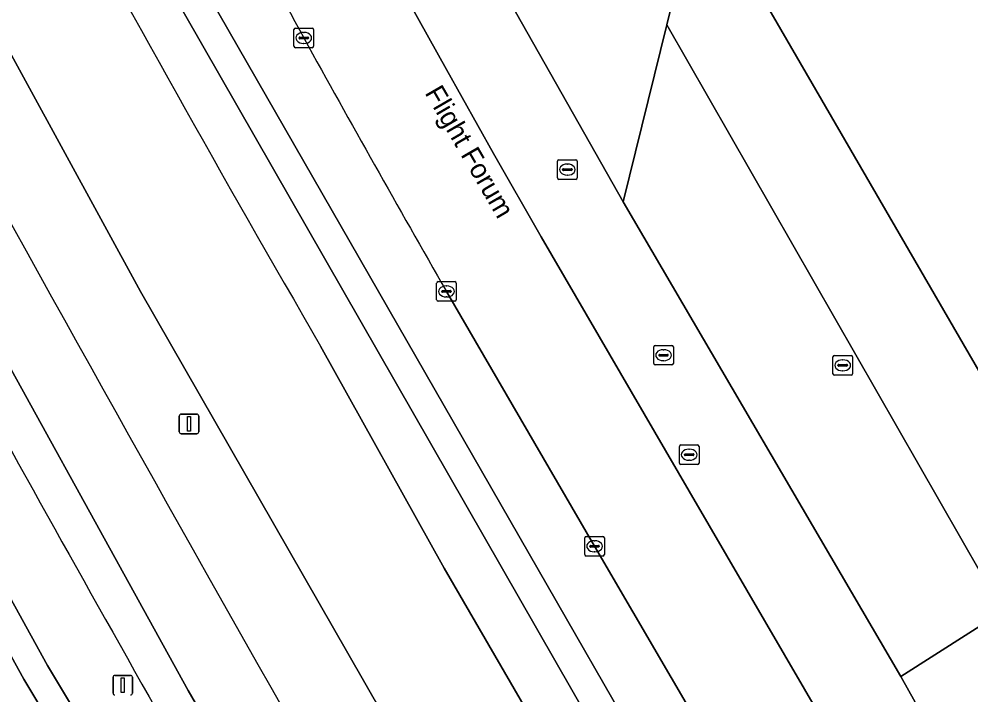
# Model space of a CAD drawing. Extents: x 155018 to 156648, y 383979 to 385733.
# Drawn here: x 155914.11 to 155962.62, y 384865.44 to 384899.91 of the extents above; entities that cross this region are included whole.
import ezdxf

# ---------------------------------------------------------------- set-up
doc = ezdxf.new("R2010")
doc.units = 0
for name, color, linetype in [('IMGEO_Berm_groen', 7, 'Continuous'), ('IMGEO_Fietspad_gesloten', 7, 'Continuous'), ('IMGEO_Greppel_droge_sloot', 7, 'Continuous'), ('IMGEO_Groenvoorziening', 7, 'Continuous'), ('IMGEO_Kolk', 7, 'Continuous'), ('IMGEO_Lichtmast', 7, 'Continuous'), ('IMGEO_Oever', 7, 'Continuous'), ('IMGEO_Openbare_ruimte_label', 7, 'Continuous'), ('IMGEO_Parkeervlak_gesloten', 7, 'Continuous'), ('IMGEO_Parkeervlak_open', 7, 'Continuous'), ('IMGEO_Rijbaan_lokaal_gesloten', 7, 'Continuous'), ('IMGEO_Rijbaan_lokaal_open', 7, 'Continuous'), ('IMGEO_Rijbaan_regionaal_gesloten', 7, 'Continuous'), ('IMGEO_Rioolput', 7, 'Continuous'), ('IMGEO_Verkeerseiland_groen', 7, 'Continuous'), ('IMGEO_Voetpad_gesloten', 7, 'Continuous'), ('IMGEO_Waterloop', 7, 'Continuous')]:
    doc.layers.add(name, color=color, linetype=linetype)

msp = doc.modelspace()

# ---------------------------------------------------------------- linework, layer by layer
at = {"layer": 'IMGEO_Berm_groen'}
for points in [[(155968.307, 384802.15), (155931.668, 384866.172), (155920.302, 384886.009), (155902.596, 384918.444), (155898.732, 384925.896), (155894.98, 384933.155)], [(155970.759, 384878.339), (155969.52, 384880.471), (155965.298, 384878.033), (155951.454, 384901.936), (155956.211, 384904.782), (155955.257, 384906.561), (155953.497, 384906.937), (155948.14, 384903.802), (155947.503, 384901.164), (155947.122, 384899.613), (155964.252, 384869.701), (155964.8, 384870.05), (155970.427, 384873.861)]]:
    msp.add_lwpolyline(points, dxfattribs=at)
msp.add_arc((158231.037, 386171.485), 2648.321, 208.928524, 210.788417, dxfattribs=at)
at = {"layer": 'IMGEO_Fietspad_gesloten'}
msp.add_lwpolyline([(155891.806, 384922.174), (155901.33, 384904.485), (155909.95, 384888.824), (155922.729, 384865.669), (155940.418, 384835.124), (155959.664, 384802.736), (155961.452, 384799.64), (155970.449, 384784.821), (155975.409, 384776.674)], dxfattribs=at)
msp.add_arc((158231.037, 386171.485), 2648.321, 208.928524, 210.788417, dxfattribs=at)
at = {"layer": 'IMGEO_Greppel_droge_sloot'}
for points in [[(155907.015, 384928.97), (155911.536, 384920.207), (155922.534, 384900.162), (155961.154, 384832.74)], [(155962.543, 384833.543), (155923.838, 384901.004), (155912.886, 384920.904), (155908.561, 384929.213)]]:
    msp.add_lwpolyline(points, dxfattribs=at)
at = {"layer": 'IMGEO_Groenvoorziening'}
msp.add_lwpolyline([(155897.525, 384899.54), (155897.874, 384899.054), (155915.552, 384866.936), (155929.251, 384844.105), (155931.997, 384845.617)], dxfattribs=at)
msp.add_arc((157919.27, 385992.931), 2294.686, 208.789811, 209.999159, dxfattribs=at)
at = {"layer": 'IMGEO_Kolk'}
for p, q in [((155928.119, 384898.515), (155928.119, 384899.367)), ((155928.194, 384899.441), (155929.046, 384899.441)), ((155928.607, 384899.221), (155928.632, 384899.221)), ((155929.12, 384899.367), (155929.12, 384898.515)), ((155928.378, 384898.935), (155928.378, 384898.947)), ((155928.816, 384898.898), (155928.418, 384898.898)), ((155928.421, 384898.984), (155928.819, 384898.984)), ((155928.862, 384898.947), (155928.862, 384898.935)), ((155929.046, 384898.441), (155928.194, 384898.441)), ((155928.63, 384898.661), (155928.605, 384898.661)), ((155935.392, 384885.588), (155935.392, 384886.44)), ((155935.467, 384886.514), (155936.319, 384886.514)), ((155935.88, 384886.294), (155935.905, 384886.294)), ((155936.393, 384886.44), (155936.393, 384885.588)), ((155935.651, 384886.008), (155935.651, 384886.02)), ((155936.089, 384885.971), (155935.691, 384885.971)), ((155935.694, 384886.057), (155936.092, 384886.057)), ((155935.903, 384885.734), (155935.878, 384885.734)), ((155936.135, 384886.02), (155936.135, 384886.008)), ((155936.319, 384885.514), (155935.467, 384885.514)), ((155943.013, 384873.52), (155943.865, 384873.52)), ((155942.938, 384872.594), (155942.938, 384873.446)), ((155943.197, 384873.014), (155943.197, 384873.026)), ((155943.24, 384873.063), (155943.638, 384873.063)), ((155943.426, 384873.3), (155943.451, 384873.3)), ((155943.681, 384873.026), (155943.681, 384873.014)), ((155943.939, 384873.446), (155943.939, 384872.594)), ((155943.865, 384872.52), (155943.013, 384872.52)), ((155943.635, 384872.977), (155943.237, 384872.977)), ((155943.449, 384872.74), (155943.424, 384872.74))]:
    msp.add_line(p, q, dxfattribs=at)
for points in [[(155928.119, 384898.515), (155928.119, 384899.367)], [(155928.194, 384899.441), (155929.046, 384899.441)], [(155929.12, 384899.367), (155929.12, 384898.515)], [(155929.046, 384898.441), (155928.194, 384898.441)], [(155935.392, 384885.588), (155935.392, 384886.44)], [(155935.467, 384886.514), (155936.319, 384886.514)], [(155936.393, 384886.44), (155936.393, 384885.588)], [(155936.319, 384885.514), (155935.467, 384885.514)], [(155943.013, 384873.52), (155943.865, 384873.52)], [(155942.938, 384872.594), (155942.938, 384873.446)], [(155943.939, 384873.446), (155943.939, 384872.594)], [(155943.865, 384872.52), (155943.013, 384872.52)]]:
    msp.add_lwpolyline(points, dxfattribs=at)
for centre, radius, start, end in [((155928.196, 384899.365), 0.0765, 91.552, 178.448), ((155928.196, 384899.365), 0.0765, 91.552, 178.448), ((155929.044, 384899.365), 0.0765, 1.552, 88.448), ((155929.044, 384899.365), 0.0765, 1.552, 88.448), ((155928.418, 384898.944), 0.0403, 85.8775, 175.7526), ((155928.415, 384898.934), 0.0366, 178.938, 274.7102), ((155928.819, 384898.941), 0.043, 264.8664, 352.4533), ((155928.823, 384898.946), 0.0386, 1.7309, 96.639), ((155928.196, 384898.517), 0.0765, 181.552, 268.448), ((155928.196, 384898.517), 0.0765, 181.552, 268.448), ((155929.044, 384898.517), 0.0765, 271.552, 358.448), ((155929.044, 384898.517), 0.0765, 271.552, 358.448), ((155935.469, 384886.438), 0.0765, 91.552, 178.448), ((155935.469, 384886.438), 0.0765, 91.552, 178.448), ((155936.317, 384886.438), 0.0765, 1.552, 88.448), ((155936.317, 384886.438), 0.0765, 1.552, 88.448), ((155935.691, 384886.017), 0.0403, 85.8775, 175.7526), ((155935.688, 384886.007), 0.0366, 178.938, 274.7102), ((155936.092, 384886.014), 0.043, 264.8664, 352.4533), ((155936.096, 384886.019), 0.0386, 1.7309, 96.639), ((155935.469, 384885.59), 0.0765, 181.552, 268.448), ((155935.469, 384885.59), 0.0765, 181.552, 268.448), ((155936.317, 384885.59), 0.0765, 271.552, 358.448), ((155936.317, 384885.59), 0.0765, 271.552, 358.448), ((155943.015, 384873.444), 0.0765, 91.552, 178.448), ((155943.015, 384873.444), 0.0765, 91.552, 178.448), ((155943.863, 384873.444), 0.0765, 1.552, 88.448), ((155943.863, 384873.444), 0.0765, 1.552, 88.448), ((155943.237, 384873.023), 0.0403, 85.8775, 175.7526), ((155943.234, 384873.013), 0.0366, 178.938, 274.7102), ((155943.638, 384873.02), 0.043, 264.8664, 352.4533), ((155943.642, 384873.025), 0.0386, 1.7309, 96.639), ((155943.015, 384872.596), 0.0765, 181.552, 268.448), ((155943.015, 384872.596), 0.0765, 181.552, 268.448), ((155943.863, 384872.596), 0.0765, 271.552, 358.448), ((155943.863, 384872.596), 0.0765, 271.552, 358.448)]:
    msp.add_arc(centre, radius, start, end, dxfattribs=at)
for centre, major_axis, ratio, start_param, end_param in [((155928.606, 384898.941), (-0.387, 0.002), 0.722429, 4.712389, 7.853982), ((155928.631, 384898.941), (-0.39, 0.002), 0.717154, 1.570796, 4.712389), ((155935.879, 384886.014), (-0.387, 0.002), 0.722429, 4.712389, 7.853982), ((155935.904, 384886.014), (-0.39, 0.002), 0.717154, 1.570796, 4.712389), ((155943.425, 384873.02), (-0.387, 0.002), 0.722429, 4.712389, 7.853982), ((155943.45, 384873.02), (-0.39, 0.002), 0.717154, 1.570796, 4.712389)]:
    msp.add_ellipse(centre, major_axis=major_axis, ratio=ratio, start_param=start_param, end_param=end_param, dxfattribs=at)
at = {"layer": 'IMGEO_Lichtmast'}
for p, q in [((155922.276, 384878.86), (155922.276, 384879.66)), ((155922.276, 384879.66), (155922.276, 384878.86)), ((155922.376, 384879.76), (155923.166, 384879.76)), ((155923.166, 384879.76), (155922.376, 384879.76)), ((155923.266, 384879.66), (155923.266, 384878.86)), ((155923.266, 384878.86), (155923.266, 384879.66)), ((155923.166, 384878.76), (155922.376, 384878.76)), ((155922.376, 384878.76), (155923.166, 384878.76)), ((155918.897, 384865.537), (155918.897, 384866.337)), ((155918.897, 384866.337), (155918.897, 384865.537)), ((155918.997, 384866.437), (155919.787, 384866.437)), ((155919.787, 384866.437), (155918.997, 384866.437)), ((155919.887, 384866.337), (155919.887, 384865.537)), ((155919.887, 384865.537), (155919.887, 384866.337))]:
    msp.add_line(p, q, dxfattribs=at)
for points in [[(155922.696, 384879.635), (155922.846, 384879.635), (155922.846, 384878.885), (155922.696, 384878.885), (155922.696, 384879.635)], [(155919.317, 384866.312), (155919.467, 384866.312), (155919.467, 384865.562), (155919.317, 384865.562), (155919.317, 384866.312)]]:
    msp.add_lwpolyline(points, dxfattribs=at)
for centre, start, end in [((155922.376, 384879.66), 90, 180), ((155922.376, 384879.66), 90, 180), ((155923.166, 384879.66), 0, 90), ((155923.166, 384879.66), 360, 90), ((155922.376, 384878.86), 180, 270), ((155922.376, 384878.86), 180, 270), ((155923.166, 384878.86), 270, 0), ((155923.166, 384878.86), 270, 0), ((155918.997, 384866.337), 90, 180), ((155918.997, 384866.337), 90, 180), ((155919.787, 384866.337), 0, 90), ((155919.787, 384866.337), 360, 90), ((155918.997, 384865.537), 180, 270), ((155918.997, 384865.537), 180, 270), ((155919.787, 384865.537), 270, 0), ((155919.787, 384865.537), 270, 0)]:
    msp.add_arc(centre, 0.1, start, end, dxfattribs=at)
at = {"layer": 'IMGEO_Oever'}
for points in [[(155965.324, 384781.723), (155958.557, 384793.522), (155956.272, 384797.883), (155953.363, 384803.433), (155946.914, 384814.668), (155941.514, 384823.667), (155929.251, 384844.105), (155915.552, 384866.936), (155897.874, 384899.054), (155897.525, 384899.54)], [(155896.704, 384898.316), (155914.355, 384866.248), (155928.067, 384843.395), (155940.33, 384822.957), (155945.723, 384813.969), (155952.153, 384802.769), (155955.049, 384797.242), (155957.308, 384792.919), (155960.889, 384784.915)]]:
    msp.add_lwpolyline(points, dxfattribs=at)
at = {"layer": 'IMGEO_Parkeervlak_gesloten'}
for points in [[(155981.253, 384820.042), (155973.203, 384833.364), (155971.597, 384835.865), (155963.834, 384849.111), (155956.062, 384862.435), (155948.253, 384875.822), (155940.718, 384888.798), (155938.292, 384893.055), (155935.89, 384897.326), (155933.51, 384901.609), (155931.147, 384906.043), (155928.826, 384910.5), (155926.547, 384914.979), (155926.098, 384915.88), (155925.651, 384916.782), (155925.205, 384917.685), (155918.109, 384932.502), (155912.529, 384944.815)], [(155980.921, 384915.2), (155979.219, 384918.159), (155974.453, 384915.535), (155973.423, 384917.252), (155973.946, 384918.903), (155967.476, 384915.117), (155969.12, 384914.261), (155969.886, 384912.863), (155960.603, 384907.493), (155959.569, 384909.203), (155959.871, 384910.667), (155953.497, 384906.937), (155955.257, 384906.561), (155956.211, 384904.782), (155951.454, 384901.936), (155965.298, 384878.033), (155969.52, 384880.471), (155970.759, 384878.339)], [(155935.893, 384886.014), (155943.439, 384873.02), (155951.25, 384859.629), (155959.025, 384846.299), (155966.849, 384832.951), (155969.799, 384828.356), (155972.403, 384824.534), (155976.142, 384819.299), (155978.271, 384816.549), (155980.512, 384819.861), (155980.596, 384819.986)]]:
    msp.add_lwpolyline(points, dxfattribs=at)
for centre, radius, start, end in [((156400.107, 385153.11), 535.632, 206.69467, 208.32823), ((156736.167, 385344.774), 922.442, 208.902362, 209.823666)]:
    msp.add_arc(centre, radius, start, end, dxfattribs=at)
at = {"layer": 'IMGEO_Parkeervlak_open'}
msp.add_lwpolyline([(155947.122, 384899.613), (155944.902, 384890.583), (155959.041, 384866.377), (155964.252, 384869.701)], close=True, dxfattribs=at)
at = {"layer": 'IMGEO_Rijbaan_lokaal_gesloten'}
for points in [[(155912.529, 384944.815), (155918.109, 384932.502), (155925.205, 384917.685), (155925.651, 384916.782), (155926.098, 384915.88), (155926.547, 384914.979), (155928.826, 384910.5), (155931.147, 384906.043), (155933.51, 384901.609), (155935.89, 384897.326), (155938.292, 384893.055), (155940.718, 384888.798), (155948.253, 384875.822), (155956.062, 384862.435), (155963.834, 384849.111), (155971.597, 384835.865), (155973.203, 384833.364), (155981.253, 384820.042), (155983.336, 384816.735), (155984.592, 384814.908), (155987.12, 384811.227), (155988.5, 384809.261), (155990.13, 384807.18)], [(155976.357, 384836.745), (155965.559, 384855.153), (155963.825, 384857.831), (155959.041, 384866.377), (155944.902, 384890.583), (155938.324, 384902.21), (155934.031, 384910.194)], [(155993.943, 384883.464), (156014.432, 384895.282), (156010.159, 384902.636), (156005.328, 384899.852), (156004.508, 384901.232), (156002.81, 384900.264), (155997.133, 384896.963), (155997.854, 384895.599), (155994.407, 384893.715), (155993.069, 384892.655), (155983.572, 384887.264), (155982.48, 384886.602), (155982.301, 384886.448), (155983.278, 384884.804), (155983.874, 384882.97), (155981.889, 384881.625), (155980.413, 384880.626), (155979.235, 384879.828), (155970.427, 384873.861), (155964.8, 384870.05), (155964.252, 384869.701), (155959.041, 384866.377), (155963.825, 384857.831), (155964.057, 384860.389)]]:
    msp.add_lwpolyline(points, dxfattribs=at)
at = {"layer": 'IMGEO_Rijbaan_lokaal_open'}
msp.add_lwpolyline([(155970.829, 384923.546), (155950.99, 384911.918), (155943.564, 384907.565), (155942.381, 384907.891), (155934.031, 384910.194), (155938.324, 384902.21), (155944.902, 384890.583), (155947.122, 384899.613), (155947.503, 384901.164), (155948.14, 384903.802), (155953.497, 384906.937), (155959.871, 384910.667), (155967.476, 384915.117)], dxfattribs=at)
at = {"layer": 'IMGEO_Rijbaan_regionaal_gesloten'}
for points in [[(155894.98, 384933.155), (155898.732, 384925.896), (155902.596, 384918.444), (155920.302, 384886.009), (155931.668, 384866.172), (155968.307, 384802.15)], [(155958.037, 384833.375), (155954.35, 384839.888), (155935.774, 384871.908), (155929.479, 384883.226)]]:
    msp.add_lwpolyline(points, dxfattribs=at)
msp.add_arc((156792.642, 385383.905), 997.862, 206.71492, 210.115927, dxfattribs=at)
at = {"layer": 'IMGEO_Rioolput'}
for p, q in [((155941.551, 384891.802), (155941.551, 384892.654)), ((155941.626, 384892.728), (155942.478, 384892.728)), ((155942.039, 384892.508), (155942.064, 384892.508)), ((155942.552, 384892.654), (155942.552, 384891.802)), ((155941.81, 384892.222), (155941.81, 384892.234)), ((155942.248, 384892.185), (155941.85, 384892.185)), ((155941.853, 384892.271), (155942.251, 384892.271)), ((155942.062, 384891.948), (155942.037, 384891.948)), ((155942.294, 384892.234), (155942.294, 384892.222)), ((155942.478, 384891.728), (155941.626, 384891.728)), ((155946.455, 384882.338), (155946.455, 384883.19)), ((155946.53, 384883.264), (155947.382, 384883.264)), ((155947.456, 384883.19), (155947.456, 384882.338)), ((155946.714, 384882.758), (155946.714, 384882.77)), ((155947.152, 384882.721), (155946.754, 384882.721)), ((155946.757, 384882.807), (155947.155, 384882.807)), ((155946.943, 384883.044), (155946.968, 384883.044)), ((155947.198, 384882.77), (155947.198, 384882.758)), ((155955.662, 384882.747), (155956.514, 384882.747)), ((155947.382, 384882.264), (155946.53, 384882.264)), ((155946.966, 384882.484), (155946.941, 384882.484)), ((155955.587, 384881.821), (155955.587, 384882.673)), ((155955.846, 384882.241), (155955.846, 384882.253)), ((155956.284, 384882.204), (155955.886, 384882.204)), ((155955.889, 384882.29), (155956.287, 384882.29)), ((155956.075, 384882.527), (155956.1, 384882.527)), ((155956.33, 384882.253), (155956.33, 384882.241)), ((155956.588, 384882.673), (155956.588, 384881.821)), ((155956.514, 384881.747), (155955.662, 384881.747)), ((155956.098, 384881.967), (155956.073, 384881.967)), ((155947.762, 384877.262), (155947.762, 384878.114)), ((155947.837, 384878.188), (155948.689, 384878.188)), ((155948.25, 384877.968), (155948.275, 384877.968)), ((155948.763, 384878.114), (155948.763, 384877.262)), ((155948.021, 384877.682), (155948.021, 384877.694)), ((155948.459, 384877.645), (155948.061, 384877.645)), ((155948.064, 384877.731), (155948.462, 384877.731)), ((155948.273, 384877.408), (155948.248, 384877.408)), ((155948.505, 384877.694), (155948.505, 384877.682)), ((155948.689, 384877.188), (155947.837, 384877.188))]:
    msp.add_line(p, q, dxfattribs=at)
for points in [[(155941.551, 384891.802), (155941.551, 384892.654)], [(155941.626, 384892.728), (155942.478, 384892.728)], [(155942.552, 384892.654), (155942.552, 384891.802)], [(155942.478, 384891.728), (155941.626, 384891.728)], [(155946.455, 384882.338), (155946.455, 384883.19)], [(155946.53, 384883.264), (155947.382, 384883.264)], [(155947.456, 384883.19), (155947.456, 384882.338)], [(155955.662, 384882.747), (155956.514, 384882.747)], [(155947.382, 384882.264), (155946.53, 384882.264)], [(155955.587, 384881.821), (155955.587, 384882.673)], [(155956.588, 384882.673), (155956.588, 384881.821)], [(155956.514, 384881.747), (155955.662, 384881.747)], [(155947.762, 384877.262), (155947.762, 384878.114)], [(155947.837, 384878.188), (155948.689, 384878.188)], [(155948.763, 384878.114), (155948.763, 384877.262)], [(155948.689, 384877.188), (155947.837, 384877.188)]]:
    msp.add_lwpolyline(points, dxfattribs=at)
for centre, radius, start, end in [((155941.628, 384892.652), 0.0765, 91.552, 178.448), ((155941.628, 384892.652), 0.0765, 91.552, 178.448), ((155942.476, 384892.652), 0.0765, 1.552, 88.448), ((155942.476, 384892.652), 0.0765, 1.552, 88.448), ((155941.85, 384892.231), 0.0403, 85.8775, 175.7526), ((155941.847, 384892.221), 0.0366, 178.938, 274.7102), ((155942.251, 384892.228), 0.043, 264.8664, 352.4533), ((155942.255, 384892.233), 0.0386, 1.7309, 96.639), ((155941.628, 384891.804), 0.0765, 181.552, 268.448), ((155941.628, 384891.804), 0.0765, 181.552, 268.448), ((155942.476, 384891.804), 0.0765, 271.552, 358.448), ((155942.476, 384891.804), 0.0765, 271.552, 358.448), ((155946.532, 384883.188), 0.0765, 91.552, 178.448), ((155946.532, 384883.188), 0.0765, 91.552, 178.448), ((155947.38, 384883.188), 0.0765, 1.552, 88.448), ((155947.38, 384883.188), 0.0765, 1.552, 88.448), ((155946.754, 384882.767), 0.0403, 85.8775, 175.7526), ((155946.751, 384882.757), 0.0366, 178.938, 274.7102), ((155947.155, 384882.764), 0.043, 264.8664, 352.4533), ((155947.159, 384882.769), 0.0386, 1.7309, 96.639), ((155955.664, 384882.671), 0.0765, 91.552, 178.448), ((155955.664, 384882.671), 0.0765, 91.552, 178.448), ((155956.512, 384882.671), 0.0765, 1.552, 88.448), ((155956.512, 384882.671), 0.0765, 1.552, 88.448), ((155946.532, 384882.34), 0.0765, 181.552, 268.448), ((155946.532, 384882.34), 0.0765, 181.552, 268.448), ((155947.38, 384882.34), 0.0765, 271.552, 358.448), ((155947.38, 384882.34), 0.0765, 271.552, 358.448), ((155955.886, 384882.25), 0.0403, 85.8775, 175.7526), ((155955.883, 384882.24), 0.0366, 178.938, 274.7102), ((155956.287, 384882.247), 0.043, 264.8664, 352.4533), ((155956.291, 384882.252), 0.0386, 1.7309, 96.639), ((155955.664, 384881.823), 0.0765, 181.552, 268.448), ((155955.664, 384881.823), 0.0765, 181.552, 268.448), ((155956.512, 384881.823), 0.0765, 271.552, 358.448), ((155956.512, 384881.823), 0.0765, 271.552, 358.448), ((155947.839, 384878.112), 0.0765, 91.552, 178.448), ((155947.839, 384878.112), 0.0765, 91.552, 178.448), ((155948.687, 384878.112), 0.0765, 1.552, 88.448), ((155948.687, 384878.112), 0.0765, 1.552, 88.448), ((155948.061, 384877.691), 0.0403, 85.8775, 175.7526), ((155948.058, 384877.681), 0.0366, 178.938, 274.7102), ((155948.462, 384877.688), 0.043, 264.8664, 352.4533), ((155948.466, 384877.693), 0.0386, 1.7309, 96.639), ((155947.839, 384877.264), 0.0765, 181.552, 268.448), ((155947.839, 384877.264), 0.0765, 181.552, 268.448), ((155948.687, 384877.264), 0.0765, 271.552, 358.448), ((155948.687, 384877.264), 0.0765, 271.552, 358.448)]:
    msp.add_arc(centre, radius, start, end, dxfattribs=at)
for centre, major_axis, ratio, start_param, end_param in [((155942.038, 384892.228), (-0.387, 0.002), 0.722429, 4.712389, 7.853982), ((155942.063, 384892.228), (-0.39, 0.002), 0.717154, 1.570796, 4.712389), ((155946.942, 384882.764), (-0.387, 0.002), 0.722429, 4.712389, 7.853982), ((155946.967, 384882.764), (-0.39, 0.002), 0.717154, 1.570796, 4.712389), ((155956.074, 384882.247), (-0.387, 0.002), 0.722429, 4.712389, 7.853982), ((155956.099, 384882.247), (-0.39, 0.002), 0.717154, 1.570796, 4.712389), ((155948.249, 384877.688), (-0.387, 0.002), 0.722429, 4.712389, 7.853982), ((155948.274, 384877.688), (-0.39, 0.002), 0.717154, 1.570796, 4.712389)]:
    msp.add_ellipse(centre, major_axis=major_axis, ratio=ratio, start_param=start_param, end_param=end_param, dxfattribs=at)
at = {"layer": 'IMGEO_Verkeerseiland_groen'}
for points in [[(155961.154, 384832.74), (155922.534, 384900.162), (155911.536, 384920.207), (155907.015, 384928.97)], [(155908.561, 384929.213), (155912.886, 384920.904), (155923.838, 384901.004), (155962.543, 384833.543)], [(155959.025, 384846.299), (155951.25, 384859.629), (155943.439, 384873.02), (155935.893, 384886.014)], [(155929.479, 384883.226), (155935.774, 384871.908), (155954.35, 384839.888), (155958.037, 384833.375)]]:
    msp.add_lwpolyline(points, dxfattribs=at)
for centre, radius, start, end in [((156792.642, 385383.905), 997.862, 206.71492, 210.115927), ((156400.107, 385153.11), 535.632, 206.69467, 208.32823), ((156736.167, 385344.774), 922.442, 208.902362, 209.823666)]:
    msp.add_arc(centre, radius, start, end, dxfattribs=at)
at = {"layer": 'IMGEO_Voetpad_gesloten'}
msp.add_lwpolyline([(155975.409, 384776.674), (155970.449, 384784.821), (155961.452, 384799.64), (155959.664, 384802.736), (155940.418, 384835.124), (155922.729, 384865.669), (155909.95, 384888.824), (155901.33, 384904.485), (155891.806, 384922.174)], dxfattribs=at)
msp.add_arc((157919.27, 385992.931), 2294.686, 208.789811, 209.999159, dxfattribs=at)
at = {"layer": 'IMGEO_Waterloop'}
msp.add_lwpolyline([(155960.889, 384784.915), (155957.308, 384792.919), (155955.049, 384797.242), (155952.153, 384802.769), (155945.723, 384813.969), (155940.33, 384822.957), (155928.067, 384843.395), (155914.355, 384866.248), (155896.704, 384898.316)], dxfattribs=at)

# ---------------------------------------------------------------- texts
at = {"layer": 'IMGEO_Openbare_ruimte_label'}
msp.add_text('Flight Forum', height=1, rotation=300.1286, dxfattribs=at).set_placement((155934.764, 384896.144))

doc.saveas('drawing.dxf')
